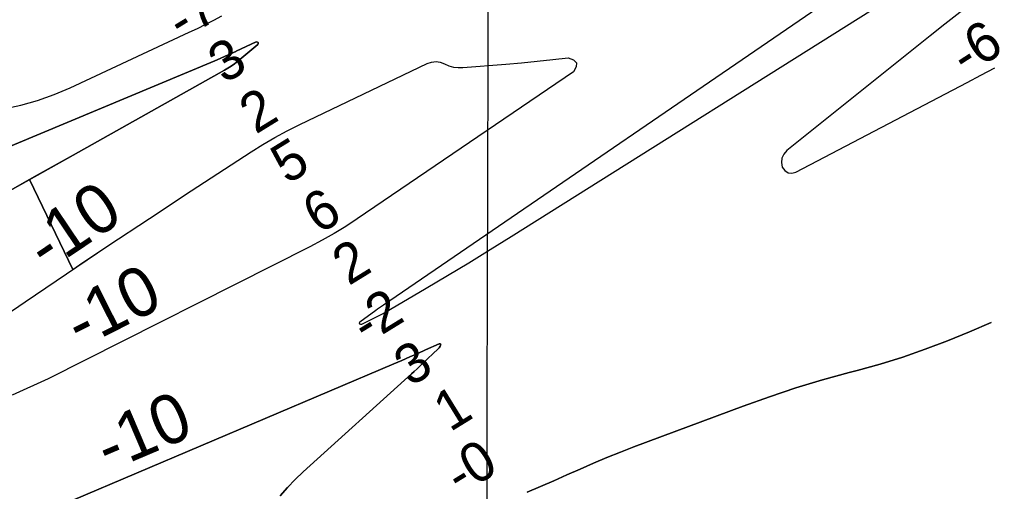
# Model space of a CAD drawing. Extents: x 3177385 to 3215275, y 903885 to 929304.
# Drawn here: x 3186040 to 3187679, y 910451 to 911249 of the extents above; entities that cross this region are included whole.
import ezdxf

# ---------------------------------------------------------------- set-up
doc = ezdxf.new("R2010")
doc.units = 0
for name, color, linetype in [('V-GRID-MAJR', 7, 'Continuous'), ('V-RIVR-RANG', 7, 'Continuous'), ('V-TOPO-DPTH', 7, 'Continuous'), ('V-TOPO-MINR', 7, 'Continuous'), ('V-TOPO-MINR-IDEN', 7, 'Continuous')]:
    doc.layers.add(name, color=color, linetype=linetype)

msp = doc.modelspace()

# ---------------------------------------------------------------- linework, layer by layer
at = {"layer": 'V-GRID-MAJR'}
msp.add_spline([(3186826.1, 909324.9), (3186842, 915385.9), (3186857.8, 921448.8), (3186873.7, 927511.8), (3186873.7, 927513.7)], degree=3, dxfattribs=at)
at = {"layer": 'V-TOPO-DPTH'}
for points in [[(3185928.5, 910994.4), (3186369.7, 911178.9), (3186378.6, 911182.7), (3186387.4, 911186.6), (3186396.3, 911190.6), (3186405, 911194.7), (3186405.6, 911194.9), (3186414.1, 911198.9), (3186422.6, 911202.9), (3186431.1, 911206.7), (3186439.7, 911210.6), (3186441.7, 911210.3), (3186442.9, 911209.6), (3186443, 911208.1), (3186442.4, 911206.2), (3186408.5, 911178.1), (3186403.1, 911173.9), (3186397.6, 911169.9), (3186391.8, 911166.2), (3186386, 911162.7), (3186130.7, 911019.6), (3186069.7, 910985.4)], [(3186028.1, 910962.1), (3186130.7, 911019.6), (3186386, 911162.7), (3186391.8, 911166.2), (3186397.6, 911169.9), (3186403.1, 911173.9), (3186408.5, 911178.1), (3186442.4, 911206.2), (3186443, 911208.1), (3186442.9, 911209.6), (3186441.7, 911210.3), (3186439.7, 911210.6), (3186431.1, 911206.7), (3186422.6, 911202.9), (3186414.1, 911198.9), (3186405.6, 911194.9), (3186405, 911194.7), (3186396.3, 911190.6), (3186387.4, 911186.6), (3186378.6, 911182.7), (3186369.7, 911178.9), (3185928.5, 910994.4)], [(3186772.5, 911168.2), (3186780.3, 911167.3), (3186788.3, 911167.3), (3186861, 911173.3), (3186887.4, 911175.6), (3186913.8, 911178.1), (3186940.1, 911180.9), (3186966.4, 911183.8), (3186975.1, 911180.4), (3186980.1, 911175.5), (3186979.5, 911168.6), (3186975.2, 911160.3), (3186610.3, 910911.9), (3186590.8, 910899.2), (3186571.1, 910887), (3186550.9, 910875.6), (3186530.4, 910864.8), (3186088.3, 910641.7), (3186027.8, 910614.3)], [(3186772.5, 911168.2), (3186780.3, 911167.3), (3186788.3, 911167.3), (3186861, 911173.3), (3186887.4, 911175.6), (3186913.8, 911178.1), (3186940.1, 911180.9), (3186966.4, 911183.8), (3186975.1, 911180.4), (3186980.1, 911175.5), (3186979.5, 911168.6), (3186975.2, 911160.3), (3186610.3, 910911.9), (3186590.8, 910899.2), (3186571.1, 910887), (3186550.9, 910875.6), (3186530.4, 910864.8), (3186088.3, 910641.7), (3186027.8, 910614.3)], [(3185786.5, 910591.9), (3186049.7, 910771.9), (3186119.3, 910819.1), (3186189.1, 910866.1), (3186259.3, 910912.7), (3186329.6, 910958.9), (3186431, 911025.1), (3186451, 911037.6), (3186471.3, 911049.5), (3186492.1, 911060.7), (3186513.3, 911071.3), (3186728.4, 911174.3), (3186735.7, 911176.5), (3186743.1, 911177.4), (3186750.3, 911176.2), (3186757.6, 911173.6), (3186764.9, 911170.5), (3186772.5, 911168.2)], [(3186069.7, 910985.4), (3186057.2, 910978.4), (3186129.9, 910826.3), (3186141.6, 910834.2), (3186189.1, 910866.1), (3186259.3, 910912.7), (3186329.6, 910958.9), (3186431, 911025.1), (3186451, 911037.6), (3186471.3, 911049.5), (3186492.1, 911060.7), (3186513.3, 911071.3), (3186728.4, 911174.3), (3186735.7, 911176.5), (3186743.1, 911177.4), (3186750.3, 911176.2), (3186757.6, 911173.6), (3186764.9, 911170.5), (3186772.5, 911168.2)], [(3186129.9, 910826.3), (3186057.2, 910978.4), (3186028.1, 910962.1), (3185925.6, 910904.6), (3185823.1, 910847), (3185720.6, 910789.4), (3185525.5, 910679.7), (3185520.6, 910676.9), (3185515.8, 910674), (3185511, 910671.1), (3185506.2, 910668.1), (3185473.5, 910647.2), (3185452.5, 910633.5), (3185431.6, 910619.7), (3185411, 910605.5), (3185390.5, 910591), (3185362.4, 910570.9), (3185328.2, 910546.1), (3185294.1, 910520.9), (3185260.4, 910495.4), (3185226.9, 910469.6), (3185044.1, 910327)], [(3185786.5, 910591.9), (3186049.7, 910771.9), (3186119.3, 910819.1), (3186129.9, 910826.3)], [(3186896.7, 910450.2), (3186919.2, 910459.8), (3186941.7, 910469.5), (3186964.1, 910479.4), (3186986.5, 910489.3), (3187008.9, 910499.1), (3187031.5, 910508.7), (3187054.2, 910517.7), (3187077.1, 910526.6), (3187261.5, 910595.7), (3187305.8, 910611.5), (3187350.3, 910626.4), (3187395.3, 910639.9), (3187440.6, 910652.4), (3187454, 910655.9), (3187492.6, 910666.7), (3187530.9, 910678.4), (3187568.7, 910691.6), (3187606.2, 910705.7), (3187643.3, 910721), (3187680.2, 910736.8)], [(3187680.2, 910736.8), (3187643.3, 910721), (3187606.2, 910705.7), (3187568.7, 910691.6), (3187530.9, 910678.4), (3187492.6, 910666.7), (3187454, 910655.9), (3187440.6, 910652.4), (3187395.3, 910639.9), (3187350.3, 910626.4), (3187305.8, 910611.5), (3187261.5, 910595.7), (3187077.1, 910526.6), (3187054.2, 910517.7), (3187031.5, 910508.7), (3187008.9, 910499.1), (3186986.5, 910489.3), (3186964.1, 910479.4), (3186941.7, 910469.5), (3186919.2, 910459.8), (3186896.7, 910450.2)], [(3186128.9, 910435.9), (3186672, 910667.1), (3186685.5, 910672.8), (3186698.9, 910678.6), (3186712.2, 910684.5), (3186725.6, 910690.5), (3186748.7, 910700.9), (3186749.7, 910700.9), (3186750.5, 910700.6), (3186750.9, 910699.9), (3186751, 910698.8), (3186750.3, 910697), (3186748.2, 910693.8), (3186746.9, 910692.4), (3186720.5, 910667.4), (3186715.8, 910663), (3186711.1, 910658.7), (3186706.3, 910654.3), (3186701.6, 910650), (3186518.9, 910484.6), (3186505.4, 910471.6), (3186492.4, 910458.2), (3186480.2, 910444.1)], [(3186480.2, 910444.1), (3186492.4, 910458.2), (3186505.4, 910471.6), (3186518.9, 910484.6), (3186701.6, 910650), (3186706.3, 910654.3), (3186711.1, 910658.7), (3186715.8, 910663), (3186720.5, 910667.4), (3186746.9, 910692.4), (3186748.2, 910693.8), (3186750.3, 910697), (3186751, 910698.8), (3186750.9, 910699.9), (3186750.5, 910700.6), (3186749.7, 910700.9), (3186748.7, 910700.9), (3186725.6, 910690.5), (3186712.2, 910684.5), (3186698.9, 910678.6), (3186685.5, 910672.8), (3186672, 910667.1), (3186128.9, 910435.9)]]:
    msp.add_lwpolyline(points, dxfattribs=at)
at = {"layer": 'V-TOPO-MINR'}
for points in [[(3187805.8, 911397), (3187677.5, 911299.4), (3187652.2, 911280), (3187627, 911260.5), (3187601.9, 911240.8), (3187577, 911220.9), (3187335, 911027.2), (3187329.9, 911021), (3187326.6, 911014.3), (3187326.2, 911006.9), (3187327.6, 910999), (3187332, 910993.3), (3187337.2, 910989.7), (3187343.5, 910989.2), (3187350.5, 910990.6), (3187639.4, 911142.4), (3187662.8, 911154.7), (3187686.2, 911166.8)], [(3187475.5, 911328.7), (3186654.6, 910766.3), (3186651.2, 910764), (3186647.9, 910761.7), (3186644.6, 910759.4), (3186641.3, 910757), (3186614.3, 910737.5), (3186613.8, 910736.8), (3186613.5, 910736.1), (3186614.1, 910734.7), (3186615.9, 910733.9), (3186617.8, 910734.2), (3186650.8, 910750.3), (3186653.9, 910751.9), (3186657, 910753.6), (3186726.5, 910794.6), (3186762.6, 910816.1), (3186798.6, 910837.8), (3186834.5, 910859.9), (3186870.2, 910882.2), (3187543.1, 911305.9)], [(3186013.5, 911097.6), (3186042.4, 911103.9), (3186070.8, 911111.6), (3186098.4, 911121.6), (3186125.6, 911133), (3186326.6, 911226.9), (3186340.6, 911233.6), (3186354.4, 911240.4), (3186368.2, 911247.5), (3186381.8, 911254.8)], [(3185928.5, 910994.4), (3186369.7, 911178.9), (3186378.6, 911182.7), (3186387.4, 911186.6), (3186396.3, 911190.6), (3186405, 911194.7), (3186405.6, 911194.9), (3186414.1, 911198.9), (3186422.6, 911202.9), (3186431.1, 911206.7), (3186439.7, 911210.6), (3186441.7, 911210.3), (3186442.9, 911209.6), (3186443, 911208.1), (3186442.4, 911206.2), (3186408.5, 911178.1), (3186403.1, 911173.9), (3186397.6, 911169.9), (3186391.8, 911166.2), (3186386, 911162.7), (3186130.7, 911019.6), (3186028.1, 910962.1)], [(3186772.5, 911168.2), (3186780.3, 911167.3), (3186788.3, 911167.3), (3186861, 911173.3), (3186887.4, 911175.6), (3186913.8, 911178.1), (3186940.1, 911180.9), (3186966.4, 911183.8), (3186975.1, 911180.4), (3186980.1, 911175.5), (3186979.5, 911168.6), (3186975.2, 911160.3), (3186610.3, 910911.9), (3186590.8, 910899.2), (3186571.1, 910887), (3186550.9, 910875.6), (3186530.4, 910864.8), (3186088.3, 910641.7), (3186027.8, 910614.3)], [(3185786.5, 910591.9), (3186049.7, 910771.9), (3186119.3, 910819.1), (3186189.1, 910866.1), (3186259.3, 910912.7), (3186329.6, 910958.9), (3186431, 911025.1), (3186451, 911037.6), (3186471.3, 911049.5), (3186492.1, 911060.7), (3186513.3, 911071.3), (3186728.4, 911174.3), (3186735.7, 911176.5), (3186743.1, 911177.4), (3186750.3, 911176.2), (3186757.6, 911173.6), (3186764.9, 911170.5), (3186772.5, 911168.2)], [(3186896.7, 910450.2), (3186919.2, 910459.8), (3186941.7, 910469.5), (3186964.1, 910479.4), (3186986.5, 910489.3), (3187008.9, 910499.1), (3187031.5, 910508.7), (3187054.2, 910517.7), (3187077.1, 910526.6), (3187261.5, 910595.7), (3187305.8, 910611.5), (3187350.3, 910626.4), (3187395.3, 910639.9), (3187440.6, 910652.4), (3187454, 910655.9), (3187492.6, 910666.7), (3187530.9, 910678.4), (3187568.7, 910691.6), (3187606.2, 910705.7), (3187643.3, 910721), (3187680.2, 910736.8)], [(3186128.9, 910435.9), (3186672, 910667.1), (3186685.5, 910672.8), (3186698.9, 910678.6), (3186712.2, 910684.5), (3186725.6, 910690.5), (3186748.7, 910700.9), (3186749.7, 910700.9), (3186750.5, 910700.6), (3186750.9, 910699.9), (3186751, 910698.8), (3186750.3, 910697), (3186748.2, 910693.8), (3186746.9, 910692.4), (3186720.5, 910667.4), (3186715.8, 910663), (3186711.1, 910658.7), (3186706.3, 910654.3), (3186701.6, 910650), (3186518.9, 910484.6), (3186505.4, 910471.6), (3186492.4, 910458.2), (3186480.2, 910444.1)]]:
    msp.add_lwpolyline(points, dxfattribs=at)

# ---------------------------------------------------------------- texts
at = {"layer": 'V-RIVR-RANG'}
for s, rotation, p in [('-7', 31.6581, (3186314.1, 911211.9)), ('-6', 32.9578, (3187637.7, 911152)), ('3', 31.6581, (3186386.1, 911138.9)), ('2', 31.6581, (3186438.8, 911053.9)), ('5', 31.6581, (3186492, 910969.2)), ('6', 31.6581, (3186545.6, 910884.8)), ('2', 31.6581, (3186595.7, 910798.1)), ('-2', 31.6581, (3186625.5, 910699)), ('3', 31.6581, (3186699.8, 910627.4)), ('1', 31.6581, (3186766.6, 910551.1)), ('-0', 31.6581, (3186783.9, 910444.3))]:
    msp.add_text(s, height=67, rotation=rotation, dxfattribs=at).set_placement(p)
at = {"layer": 'V-TOPO-MINR-IDEN'}
for rotation, p in [(33.9363, (3186085.7, 910821.6)), (26.774, (3186142.9, 910692.5)), (23.0542, (3186190.1, 910484.5))]:
    msp.add_text('-10', height=83, rotation=rotation, dxfattribs=at).set_placement(p)

doc.saveas('drawing.dxf')
